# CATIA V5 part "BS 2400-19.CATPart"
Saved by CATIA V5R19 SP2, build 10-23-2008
Part number: BS 2400-19
Bounding box of the stored display mesh (mm): x -37.351 to 37.351, y -37.351 to 37.351, z 0 to 83
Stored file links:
  C:\Users\Bora\Desktop\3D Katı model\BS serisi\BS 2400\BS 2400-19.CATPart
  C:\Program Files\Dassault Systemes\B19\intel_a\reffiles\standard\MetricThickPitch.txt
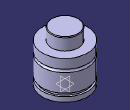
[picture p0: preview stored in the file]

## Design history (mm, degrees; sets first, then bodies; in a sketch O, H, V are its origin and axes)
Body1 (main body)
  Sketch1 on yz-plane, origin (0, 0, 0), H (0, 1, 0), V (0, 0, 1)
    point P1 (22.5, 82)
    point P3 (22.5, 82)
    point P7 (37.5, 47.5)
    point P9 (37.5, 47.5)
    point P10 (37.5, 42.5)
    point P14 (37.5, 42.5)
    line L1 (22.5, 82) -> (22.5, 63)
    arc A1 centre (21.5, 82) radius 1 from (22.5, 82) to (21.5, 83) ccw
    line L2 (37.5, 0) -> (37.5, 8)
    line L3 (37.5, 47.5) -> (37.5, 63)
    arc A2 centre (37.5, 45) radius 2.5 from (37.5, 47.5) to (37.5, 42.5) ccw
    line L4 (34.5, 13) -> (34.5, 8)
    line L5 (37.5, 13) -> (37.5, 42.5)
    line L6 (21.5, 83) -> (0, 83)
    point P15 (0, 83)
    line L7 (22.5, 63) -> (37.5, 63)
    line L8 (0, 0) -> (37.5, 0)
    line L9 (34.5, 13) -> (37.5, 13)
    line L10 (34.5, 8) -> (37.5, 8)
    coincidence: P15 V, P1 P3, P7 P9, P10 P14
    tangency: L6 A1
    horizontal: L7 H, L8 H, L9 H, L10 H
  Shaft1: profile Sketch1, axis Sketch1.V, angle 360
  Sketch2 on face of Shaft1 from Sketch1.L8, origin (0, 0, 0), H (1, 0, 0), V (0, -1, 0)
    point P1 (20, 0)
    distance P1 V = 20
  Hole1: placed by Sketch2, at (20, 0, 0) direction (0, 0, 1), diameter 6.647, depth 5, threaded "M8", thread diameter 8, thread depth 5, pitch 1.25
  CircPattern1: of Hole1, instances 4, angular step 90, axis from xy-plane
